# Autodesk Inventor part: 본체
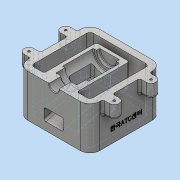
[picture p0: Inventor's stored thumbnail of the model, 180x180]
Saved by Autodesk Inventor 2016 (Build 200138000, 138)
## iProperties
Created: 2018-01
Part Number: 본체
Material: 일반
Document SubType Name: Modeling
Designer: Administrator
Density: 1 g/cm^3
Appearance: 기본값
Mass: 370.459 g
Surface Area: 834.593 cm^2
Volume: 370.459 cm^3
Author: Administrator
## Parameters: d14 = 32 mm, d15 = 15 mm, d55 = 65 mm, d56 = 0, d57 = 105 deg, d61 = 0, d62 = 19 mm, d63 = 14 mm, d64 = 47 mm, d65 = 5 mm, d68 = 32 mm, d69 = 15 mm, d70 = 180 deg, d71 = 1 mm, d81 = 15 mm, d83 = 27 mm, d85 = 0, d88 = 3.242 mm, d89 = 9 mm, d90 = 4 mm, d91 = 2 mm, d92 = 90 deg, d93 = 11 mm, d94 = 118 deg, d97 = 56 mm, d101 = 18 mm, d102 = 0, d103 = 0, d104 = 5 mm, d106 = 35 mm, d107 = 37 mm, d110 = 0, d111 = 5 mm, d113 = 15 mm, d114 = 1 mm, d115 = 2 mm, d116 = 45 deg, d117 = 3 mm, d118 = 3 mm, d119 = 3 mm, d120 = 3 mm, d121 = 3 mm, d126 = 55 mm, d127 = 0.5 mm, d128 = 0, d130 = 3 mm, d131 = 3 mm, d132 = 3 mm
